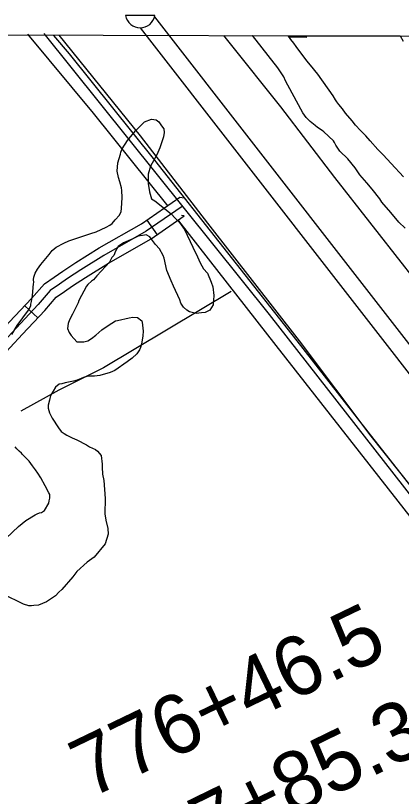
# Model space of a CAD drawing. Extents: x 3161514 to 3199414, y 831166 to 856601.
# Drawn here: x 3177544 to 3178194, y 853504 to 854820 of the extents above; entities that cross this region are included whole.
import ezdxf

# ---------------------------------------------------------------- set-up
doc = ezdxf.new("R2010")
doc.units = 0
for name, color, linetype in [('V-GRID-FRAM', 7, 'Continuous'), ('V-LEVE-TOET', 7, 'Continuous'), ('V-ROAD-CNTR', 7, 'Continuous'), ('V-SITE-VEGE', 7, 'Continuous'), ('V-SURV-IDEN', 7, 'Continuous'), ('V-SURV-LINE', 7, 'Continuous'), ('V-TOPO-SHOR', 7, 'Continuous'), ('V-WETL-SWMP', 7, 'Continuous')]:
    doc.layers.add(name, color=color, linetype=linetype)

msp = doc.modelspace()

# ---------------------------------------------------------------- linework, layer by layer
at = {"layer": 'V-GRID-FRAM'}
msp.add_lwpolyline([(3165761, 854820), (3197144.3, 854733.3), (3197102, 836546.1), (3165702.9, 836632.9), (3165761, 854820)], dxfattribs=at)
at = {"layer": 'V-LEVE-TOET'}
for points in [[(3177617.3, 854787.3), (3177754.3, 854617.3), (3177867.5, 854470.1), (3178022, 854271.8), (3178143, 854111.5), (3178278.9, 853940.4), (3178442.5, 853738.7), (3178481.8, 853695.4), (3178495, 853683.9), (3178505.5, 853675.6), (3178518.6, 853665.6), (3178545.4, 853644.2), (3178689.7, 853535.5), (3178900.1, 853390), (3179119.1, 853237.4), (3179359, 853071.5), (3179589.3, 852913.2), (3179882, 852704.8), (3180072.9, 852571.9), (3180165.3, 852509.3), (3180172.2, 852505.5)], [(3179994.3, 852911.2), (3179991.5, 852912.6), (3179985.2, 852914.7), (3179978.5, 852916), (3179968.3, 852918.8), (3179961.2, 852920.3), (3179946.6, 852925.5), (3179789.8, 853030.4), (3179512, 853221.5), (3179270.2, 853388.4), (3179044.3, 853553.3), (3178798.6, 853724.5), (3178677.8, 853812.8), (3178652.6, 853835.3), (3178632.4, 853860.7), (3178618.1, 853874.1), (3178506.2, 854013.9), (3178400.5, 854144.7), (3178274.1, 854302.4), (3178199.9, 854396.8), (3178082.4, 854547.5), (3177991.4, 854666.6), (3177903.9, 854775.2), (3177895, 854786.5)]]:
    msp.add_lwpolyline(points, dxfattribs=at)
at = {"layer": 'V-ROAD-CNTR'}
for p, q in [((3177765.6, 854475.6), (3177782.6, 854450.9)), ((3177559.7, 854331.1), (3177581.6, 854310.6))]:
    msp.add_line(p, q, dxfattribs=at)
for points in [[(3177592.2, 854789.9), (3177971.4, 854316.2), (3178263.7, 853942.1), (3178396, 853775.7), (3178430.3, 853732.9), (3178457, 853704.8), (3178482.7, 853679.1), (3178527.4, 853641.6), (3178608, 853580.7), (3178927.2, 853358), (3179165.4, 853188.9), (3179528.5, 852937.7), (3180018.6, 852597.4), (3180287.5, 852417.1), (3180694.2, 852166.9), (3181125.4, 851896.4)], [(3176695.6, 853751.5), (3176723.5, 853781.8), (3176745.3, 853800), (3176854.6, 853857.8), (3177007, 853938.5), (3177155.1, 854018.2), (3177260.9, 854069.3), (3177305.6, 854096.9), (3177339.8, 854122.9), (3177383, 854156.8), (3177413.4, 854183), (3177442.4, 854210.5), (3177492.3, 854259.1), (3177534.2, 854303.9), (3177571.2, 854343.4), (3177592.8, 854368), (3177609.6, 854379.6), (3177623.7, 854389.7), (3177646.1, 854404.1), (3177685.4, 854428.5), (3177756.5, 854469.3), (3177821.3, 854513.9), (3177828.1, 854512.9)], [(3177825.9, 854498), (3177825, 854498.2), (3177764.5, 854456.6), (3177693.1, 854415.6), (3177654.1, 854391.5), (3177632.1, 854377.3), (3177618.2, 854367.3), (3177602.9, 854356.7), (3177582.3, 854333.3), (3177545.1, 854293.6), (3177503, 854248.6), (3177452.8, 854199.7), (3177423.5, 854171.9), (3177392.5, 854145.2), (3177349, 854111), (3177314.1, 854084.5), (3177268.1, 854056.1), (3177161.9, 854004.9), (3177014.1, 853925.3), (3176861.6, 853844.6), (3176753.7, 853787.5), (3176733.9, 853770.9), (3176706.7, 853741.4)], [(3176717.7, 853731.2), (3176744.2, 853760), (3176762.1, 853774.9), (3176868.7, 853831.3), (3177021.2, 853912), (3177168.7, 853991.5), (3177275.3, 854043), (3177322.6, 854072.1), (3177358.1, 854099.1), (3177402.1, 854133.7), (3177433.5, 854160.7), (3177463.2, 854188.8), (3177513.7, 854238.1), (3177556.1, 854283.4), (3177593.4, 854323.2), (3177612.9, 854345.4), (3177626.8, 854355), (3177640.5, 854364.9), (3177662.1, 854378.8), (3177700.8, 854402.7), (3177772.5, 854443.9), (3177828.6, 854482.5), (3177823.6, 854483.2)]]:
    msp.add_lwpolyline(points, dxfattribs=at)
at = {"layer": 'V-SITE-VEGE'}
for p, q in [((3177943.4, 854786.3), (3177943.3, 854786.4)), ((3177943.3, 854786.4), (3178226, 854785.6)), ((3177985.9, 854732.1), (3177943.4, 854786.3)), ((3177996, 854717.1), (3177985.9, 854732.1)), ((3177999.2, 854710.2), (3177996, 854717.1)), ((3178017.7, 854675.8), (3177999.2, 854710.2)), ((3178028.5, 854656.5), (3178017.7, 854675.8)), ((3178033.6, 854648.3), (3178028.5, 854656.5)), ((3178040.6, 854641.5), (3178033.6, 854648.3)), ((3178048.8, 854634.7), (3178040.6, 854641.5)), ((3178053.2, 854631.6), (3178048.8, 854634.7)), ((3178060.8, 854626.6), (3178053.2, 854631.6)), ((3178063.9, 854624.1), (3178060.8, 854626.6)), ((3178079.7, 854609.2), (3178063.9, 854624.1)), ((3178081.6, 854606.1), (3178079.7, 854609.2)), ((3178083.6, 854601.7), (3178081.6, 854606.1)), ((3178090.6, 854591.7), (3178083.6, 854601.7)), ((3178103.8, 854578.6), (3178090.6, 854591.7)), ((3178116.5, 854563.7), (3178103.8, 854578.6)), ((3178124.1, 854551.8), (3178116.5, 854563.7)), ((3178136.2, 854538.1), (3178124.1, 854551.8)), ((3178145, 854527.5), (3178136.2, 854538.1)), ((3178157.7, 854511.3), (3178145, 854527.5)), ((3178161.5, 854505.7), (3178157.7, 854511.3)), ((3178176.7, 854488.2), (3178161.5, 854505.7)), ((3178190.1, 854472), (3178176.7, 854488.2)), ((3178200.8, 854462.1), (3178190.1, 854472))]:
    msp.add_line(p, q, dxfattribs=at)
for points in [[(3177634.3, 854440.5), (3177671.2, 854452.7), (3177680, 854455.9), (3177688.7, 854459.8), (3177696.8, 854463.6), (3177703.1, 854466.8), (3177706.8, 854470), (3177712.4, 854475.7), (3177719.3, 854483.9), (3177722.4, 854490.2), (3177722.9, 854495.2), (3177724.1, 854513.4), (3177723.3, 854525.3), (3177722.7, 854529.7), (3177720.1, 854539.7), (3177717.5, 854547.2), (3177715.5, 854557.9), (3177716.7, 854571.7), (3177720.9, 854586.8), (3177721.5, 854590), (3177724, 854595.6), (3177732.7, 854609.5), (3177737.7, 854615.8), (3177747, 854626.6), (3177761.3, 854641.1), (3177773.2, 854645.6), (3177781.4, 854644.4), (3177785.8, 854641.3), (3177790.2, 854634.4), (3177794, 854629.5), (3177794.7, 854623.2), (3177793.5, 854615.6), (3177787.4, 854597.4), (3177782.5, 854585.4), (3177771.9, 854566.5), (3177767.7, 854552.7), (3177767.8, 854537), (3177769.8, 854523.2), (3177773.6, 854511.3), (3177778.7, 854508.2), (3177806.5, 854485.8), (3177813.4, 854479)], [(3177813.4, 854479), (3177820.4, 854471.5), (3177828.7, 854459.7), (3177842.7, 854429.7), (3177851, 854413.4), (3177855.5, 854403.4), (3177861.2, 854393.4), (3177867.5, 854385.9), (3177873.9, 854370.9), (3177876.5, 854362.8), (3177878.5, 854348.4), (3177877.4, 854332.7), (3177871.8, 854323.8), (3177863.7, 854320), (3177857.4, 854319.3), (3177848.6, 854318), (3177837.3, 854321), (3177832.9, 854323.5), (3177827.2, 854328.5), (3177822.8, 854335.4), (3177820.8, 854341), (3177810.6, 854364.1), (3177806.2, 854372.9), (3177799.1, 854390.4), (3177794.5, 854411.1), (3177793.2, 854416.1), (3177786.9, 854427.3), (3177779.9, 854434.2), (3177773.6, 854443.5), (3177770.4, 854447.3), (3177764.1, 854450.4), (3177761.6, 854450.3), (3177750.9, 854448.4), (3177741.6, 854443.9), (3177725.9, 854436.9), (3177717.2, 854431.1), (3177712.9, 854422.9), (3177709.8, 854416), (3177706.7, 854412.2), (3177702.3, 854404.7), (3177696.1, 854397.1), (3177681.2, 854381.3), (3177675.6, 854375), (3177672.5, 854372.4), (3177666.2, 854366.7), (3177663.8, 854364.2), (3177650.8, 854340.2), (3177649.6, 854335.8), (3177640.3, 854316.9), (3177635.4, 854307.5), (3177632.9, 854301.2), (3177631.7, 854293), (3177634.9, 854286.1), (3177638.1, 854281.1), (3177647.6, 854270.5), (3177659.5, 854270.6), (3177665.8, 854271.9), (3177672, 854275.8), (3177679.5, 854281.5), (3177689.5, 854290.3), (3177700.1, 854298), (3177712.6, 854305.6), (3177716.3, 854306.2), (3177735.7, 854310.8), (3177742, 854312.1), (3177749.5, 854311.5), (3177757.1, 854306), (3177757.8, 854303.4), (3177758.4, 854298.4), (3177759.1, 854288.4), (3177758.6, 854280.2), (3177756.2, 854266.4), (3177755, 854260.7), (3177753.1, 854257), (3177748.8, 854250), (3177740.7, 854243.1), (3177732.6, 854236.7), (3177711.4, 854222.1), (3177703.9, 854218.9), (3177686.3, 854213.7), (3177677.5, 854212.4), (3177669.4, 854212.4), (3177664.4, 854211.7), (3177658.7, 854210.4), (3177648.1, 854205.9), (3177641.8, 854204), (3177628.1, 854201.4), (3177622.4, 854199.4), (3177618, 854198.8), (3177611.8, 854193.7), (3177607.5, 854187.4), (3177603.1, 854179.8), (3177601.3, 854172.3), (3177599.5, 854163.5), (3177599.5, 854158.4), (3177601.5, 854150.9), (3177605.9, 854141.6), (3177616.7, 854125.3), (3177621.2, 854119.1), (3177626.2, 854116), (3177630.7, 854112.9)], [(3177538.3, 854282.8), (3177546.9, 854298), (3177566.2, 854323.9), (3177569.9, 854330.8), (3177569.9, 854333.9), (3177571.1, 854338.3), (3177572.9, 854348.4), (3177574.6, 854367.9), (3177575.2, 854370.4), (3177574.6, 854375.4), (3177575.2, 854379.2), (3177577.6, 854386.1), (3177581.3, 854393), (3177586.9, 854400.6), (3177601.2, 854417.6), (3177606.2, 854424), (3177613, 854429.7), (3177625.5, 854436.7), (3177634.3, 854440.5)], [(3177630.7, 854112.9), (3177639.5, 854108.6), (3177647.7, 854105.5), (3177664, 854096.8), (3177669.1, 854093.7), (3177679.2, 854088.8), (3177682.3, 854086.3), (3177688.7, 854078.8), (3177690, 854064.4), (3177690.1, 854059.4), (3177690.8, 854047.5), (3177692.8, 854036.8), (3177695.5, 854006.1), (3177694.5, 853980.4), (3177696.5, 853969.7), (3177699.7, 853955.9), (3177700.4, 853946.5), (3177695.5, 853930.2), (3177676.9, 853907.4), (3177665, 853899.2), (3177647.6, 853883.3), (3177640.8, 853874.5), (3177622.1, 853853), (3177617.1, 853848.6), (3177611.5, 853842.2), (3177603.4, 853836.5), (3177596.5, 853832.1), (3177582.8, 853826.9), (3177575.2, 853826.3), (3177570.9, 853825.6), (3177566.5, 853825.6), (3177557.7, 853828.6), (3177523.6, 853845.3)], [(3177528.5, 853939.5), (3177549.1, 853959.1), (3177561.5, 853969.2), (3177577.1, 853978.8), (3177580.9, 853980.7), (3177584.7, 853982), (3177587.8, 853982.6), (3177592.8, 853986.4), (3177600.2, 853998.4), (3177600.8, 854002.2), (3177602, 854007.2), (3177602, 854012.9), (3177600.1, 854016), (3177594.3, 854027.9), (3177586.7, 854041), (3177581.6, 854049.1), (3177577.8, 854054.7), (3177572.7, 854061.6), (3177567, 854069.1), (3177556.2, 854080.3), (3177554.3, 854082.8), (3177550.5, 854085.9), (3177546.7, 854090.2), (3177543.6, 854093.3)]]:
    msp.add_lwpolyline(points, dxfattribs=at)
at = {"layer": 'V-SURV-LINE'}
msp.add_line((3177778.9, 854820), (3177729.7, 854820), dxfattribs=at)
for points in [[(3177778.4, 854817.9), (3178473.1, 853924.2)], [(3178449.4, 853905.8), (3177754.7, 854799.5)]]:
    msp.add_lwpolyline(points, dxfattribs=at)
msp.add_arc((3177754.3, 854824.5), 25, 190.3341, 349.6659, dxfattribs=at)
at = {"layer": 'V-TOPO-SHOR'}
for points in [[(3177564.3, 854788.7), (3177675, 854655.9), (3177801.1, 854498.8)], [(3180169.2, 852518), (3180089.6, 852564.5), (3179753.2, 852796.9), (3179489.8, 852978.3), (3179064.9, 853274.9), (3178644.3, 853573.7), (3178553.6, 853637.9), (3178480.6, 853702.1), (3178434.1, 853746.3), (3178385.4, 853803.9), (3178142, 854113.7), (3178024.7, 854264.2), (3177779, 854576.3), (3177635.1, 854755.5), (3177608.6, 854786.5)], [(3177818.8, 854474.5), (3177982.6, 854264.2), (3178263.7, 853905.7)], [(3177907.4, 854354.9), (3177692.7, 854226.6), (3177617.4, 854189), (3177553.2, 854153.5)]]:
    msp.add_lwpolyline(points, dxfattribs=at)
at = {"layer": 'V-WETL-SWMP'}
for p, q in [((3178003.6, 854786.2), (3178192.4, 854785.7)), ((3178005.8, 854783.3), (3178003.6, 854786.2)), ((3178005.2, 854784), (3178035.2, 854783.9)), ((3178008.1, 854779.6), (3178005.8, 854783.3)), ((3178192.4, 854785.7), (3178197, 854776.9)), ((3178012.9, 854773.7), (3178008.1, 854779.6)), ((3178017.2, 854768.1), (3178012.9, 854773.7)), ((3178034.9, 854744), (3178017.2, 854768.1)), ((3178041.1, 854736.7), (3178034.9, 854744)), ((3178053.4, 854721.6), (3178041.1, 854736.7)), ((3178079.1, 854684.9), (3178053.4, 854721.6)), ((3178083.3, 854678.4), (3178079.1, 854684.9)), ((3178085.3, 854675), (3178083.3, 854678.4)), ((3178088.8, 854670.3), (3178085.3, 854675)), ((3178095, 854663), (3178088.8, 854670.3)), ((3178100.4, 854655.7), (3178095, 854663)), ((3178111.5, 854642.5), (3178100.4, 854655.7)), ((3178117.2, 854635.3), (3178111.5, 854642.5)), ((3178125.5, 854626.3), (3178117.2, 854635.3)), ((3178134.6, 854617.3), (3178125.5, 854626.3)), ((3178141.7, 854608.9), (3178134.6, 854617.3)), ((3178154.5, 854594.7), (3178141.7, 854608.9)), ((3178163.6, 854585.4), (3178154.5, 854594.7)), ((3178177, 854570.9), (3178163.6, 854585.4)), ((3178198, 854548.5), (3178177, 854570.9))]:
    msp.add_line(p, q, dxfattribs=at)
msp.add_arc((3178040.4, 854784.4), 35.2, 177.0374, 180.4764, dxfattribs=at)

# ---------------------------------------------------------------- texts
at = {"layer": 'V-SURV-IDEN'}
for s, rotation, p in [('776+46.5', 25.7283, (3177669.1, 853500.1)), ('777+85.3', 25.9849, (3177736.9, 853338.4)), ('779+14.0', 27.1505, (3177886.5, 853198.5))]:
    msp.add_text(s, height=100, rotation=rotation, dxfattribs=at).set_placement(p)

doc.saveas('drawing.dxf')
